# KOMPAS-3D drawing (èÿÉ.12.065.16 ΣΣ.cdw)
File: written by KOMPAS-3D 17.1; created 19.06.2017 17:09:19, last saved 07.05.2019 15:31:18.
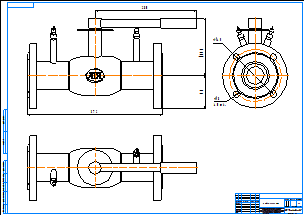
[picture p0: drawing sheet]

Sheet 1: A1, landscape

Title block, sheet 1: name: КШР.12.065.16 фф; material: Внимание! Данный продукт является объектом авторского права ООО «Торговый Дом АДЛ». / Запрещается изменение, копирование, распространение / (в том числе путем копирования на другие сайты и ресурсы в Интернете) / или любое иное использование информации и объектов без предварительного / согласия правообладателя (ООО «Торговый Дом АДЛ»).; scale: 1:1; sheets: 1; organisation: ООО "Торговый дом АДЛ"; sheet format: A1; stored path: C:\Users\tra\Desktop\2д чертежи\Шаровые краны БИВАЛ\КШР_Бивал_серия_12\KOMPAS 2D\КШР.12.065.16 фф.cdw

Views: Спереди 1, Проекционный вид 2, Проекционный вид 3
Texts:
  Klimkovich
  ADL
Dimensions and other numbers on the sheet: 372; 280; 159,3; 90; 145; 18; 4 Отв.; 1:1; 1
